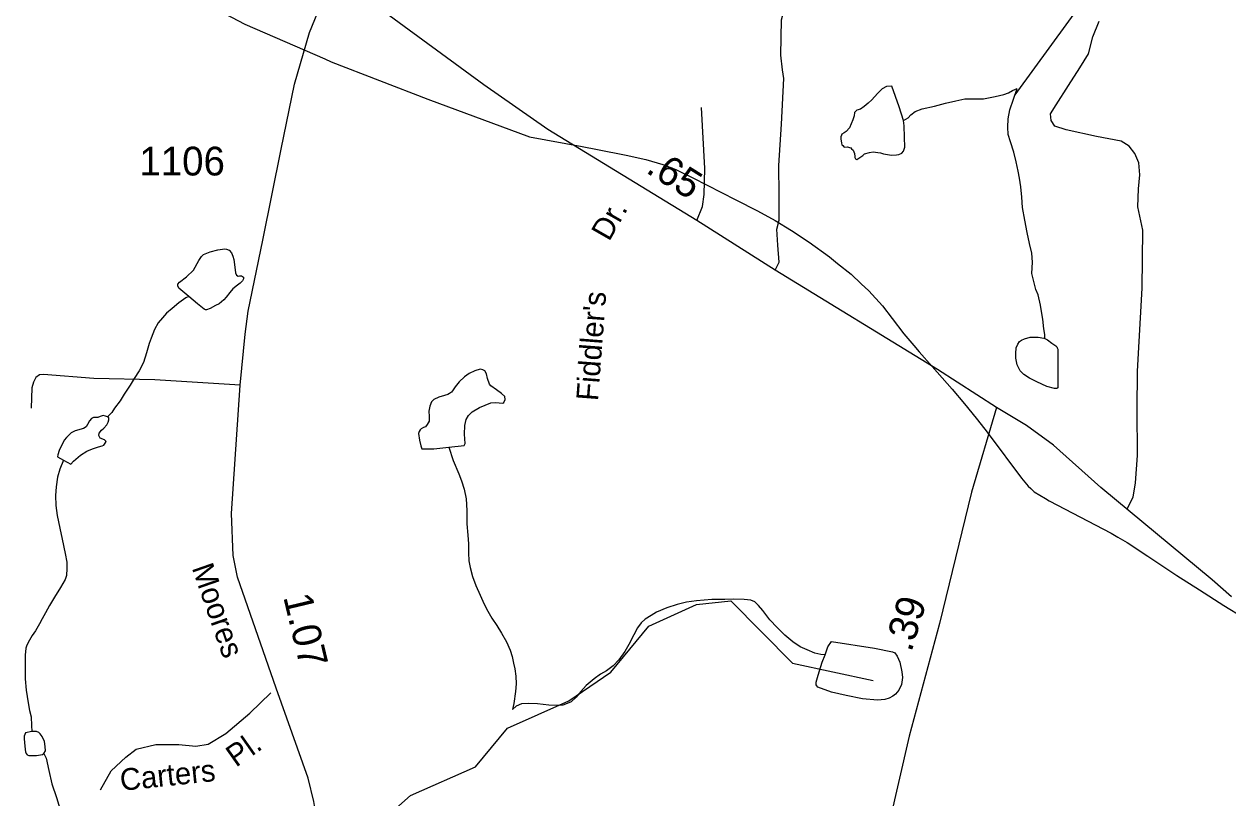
# Model space of a CAD drawing. Extents: x 2126262 to 2293712, y 749403 to 919119.
# Drawn here: x 2171233 to 2176471, y 814779 to 818143 of the extents above; entities that cross this region are included whole.
import ezdxf

# ---------------------------------------------------------------- set-up
doc = ezdxf.new("R2010")
doc.units = 0
for name, color, linetype in [('Exist Hydrographic Creek Single Shore', 7, 'Continuous'), ('Exist Hydrographic Misc Water Feature', 7, 'Continuous'), ('Exist Road Non-System Type 51', 7, 'Continuous'), ('Exist Road Non-System Type 51 Label', 7, 'Continuous'), ('Exist Road Secondary Mileage Hundredths English Label', 7, 'Continuous'), ('Exist Road Secondary Type 51 Attributed', 7, 'Continuous'), ('Exist Road Secondary Type 51 Label', 7, 'Continuous'), ('Exist Road Secondary Type 51 Number Label', 7, 'Continuous')]:
    doc.layers.add(name, color=color, linetype=linetype)

msp = doc.modelspace()

# ---------------------------------------------------------------- linework, layer by layer
at = {"layer": 'Exist Hydrographic Creek Single Shore'}
msp.add_lwpolyline([(2171499.6, 814356), (2171665.7, 814539.5), (2171815.6, 814588.9), (2171948.7, 814582.9), (2172168.9, 814545.8), (2172252.6, 814528.2), (2172286.8, 814534.4), (2172309.5, 814522), (2172367.5, 814522), (2172416.1, 814524.1), (2172430.6, 814507.5), (2172454.4, 814509.6), (2172509.2, 814516.8), (2172656.7, 814561.7), (2172913.6, 814789.3), (2173196.6, 814914.7), (2173336.7, 815082.4), (2173602.6, 815201.6), (2173785.7, 815325.8), (2173950.6, 815525.8), (2174158.7, 815619.9), (2174308.6, 815636.5), (2174576.6, 815365.2), (2174926.6, 815289.1)], dxfattribs=at)
at = {"layer": 'Exist Hydrographic Misc Water Feature'}
for p, q in [((2172541.4, 817992.3), (2172569.5, 817980)), ((2174571.4, 817245.7), (2174648.5, 817195))]:
    msp.add_line(p, q, dxfattribs=at)
for points in [[(2175545.7, 817835.3), (2176000.7, 818462.3), (2176057.7, 818680.9), (2176131.7, 818820.5), (2176239.8, 818906.8), (2176297.6, 818987.6), (2176369.4, 819487.4)], [(2171958.4, 818267.5), (2172193.4, 818143.6), (2172541.4, 817992.3)], [(2171958.4, 818267.5), (2172193.4, 818143.6), (2172541.4, 817992.3)], [(2172569.5, 817980), (2172989.2, 817816.7), (2173431.3, 817653.3), (2173661.4, 817611.7), (2173728.2, 817598.4)], [(2172569.5, 817980), (2172989.2, 817816.7), (2173431.3, 817653.3), (2173661.4, 817611.7), (2173728.2, 817598.4)], [(2175058.8, 817724.4), (2175040.6, 817784.3), (2175008.2, 817874.1), (2174986, 817872), (2174966.1, 817861.8), (2174946, 817841.7), (2174922.2, 817813.6), (2174906.2, 817799.5), (2174888.6, 817785.4), (2174872.6, 817773.3), (2174856.6, 817769.3), (2174850.5, 817763.2), (2174846.6, 817759.2), (2174844.7, 817745.2), (2174838.8, 817727.2), (2174825, 817693.1), (2174809.1, 817677), (2174801.1, 817671), (2174791.4, 817664.9), (2174789.4, 817660.9), (2174787.3, 817652.9), (2174787.3, 817642.9), (2174789.4, 817626.9), (2174791.6, 817618.9), (2174795.5, 817614.9), (2174801.7, 817609), (2174813.6, 817609.1), (2174829.6, 817605.1), (2174833.7, 817601.2), (2174839.6, 817595.2), (2174845.6, 817581.3), (2174847.8, 817567.3), (2174847.8, 817563.3), (2174849.9, 817557.3), (2174855.8, 817555.3), (2174859.9, 817557.3), (2174869.7, 817563.4), (2174881.8, 817571.5), (2174889.6, 817579.5), (2174911.6, 817585.6), (2174927.6, 817587.7), (2174947.7, 817585.8), (2174959.6, 817583.9), (2174971.7, 817579.9), (2175007.5, 817574.1), (2175029.5, 817574.3), (2175039.5, 817576.3), (2175051.6, 817582.4), (2175059.6, 817590.4), (2175065.6, 817608.4), (2175063.3, 817652.5), (2175062.9, 817700.4), (2175058.8, 817724.4)], [(2175058.8, 817724.4), (2175078.9, 817736.5), (2175090.6, 817748.6), (2175110.5, 817762.7), (2175140.6, 817774.8), (2175194.3, 817787.1), (2175242.3, 817799.4), (2175286.4, 817809.6), (2175326.4, 817817.9), (2175364.1, 817818.1), (2175408, 817818.3), (2175458, 817828.6), (2175496, 817836.9), (2175516.1, 817844.9), (2175533.9, 817855), (2175553.8, 817863.2)], [(2175673.8, 816776.1), (2175673.8, 816794.1), (2175669.7, 816818.1), (2175665.6, 816860), (2175659.4, 816894), (2175655.1, 816922), (2175644.8, 816965.9), (2175634.8, 816989.8), (2175626.6, 817023.8), (2175618.4, 817059.7), (2175620, 817107.7), (2175617.8, 817147.7), (2175607.5, 817189.6), (2175597.3, 817237.6), (2175587, 817291.5), (2175576.8, 817345.4), (2175574.5, 817391.4), (2175570.4, 817435.3), (2175564.1, 817473.2), (2175557.9, 817503.3), (2175549.5, 817545.2), (2175539.2, 817587.2), (2175525.1, 817631), (2175515, 817663), (2175512.8, 817695), (2175514.6, 817730.9), (2175522.2, 817771), (2175538, 817817), (2175553.8, 817863.2)], [(2173728.2, 817598.4), (2173853.1, 817573.7), (2173938.4, 817554.4), (2174011.4, 817533.7), (2174069.2, 817511.2), (2174143.2, 817475.2), (2174330.3, 817379.9)], [(2173728.2, 817598.4), (2173853.1, 817573.7), (2173938.4, 817554.4), (2174011.4, 817533.7), (2174069.2, 817511.2), (2174143.2, 817475.2), (2174330.3, 817379.9)], [(2174330.3, 817379.9), (2174423.3, 817331), (2174500.2, 817288.9), (2174571.4, 817245.7)], [(2174330.3, 817379.9), (2174423.3, 817331), (2174500.2, 817288.9), (2174571.4, 817245.7)], [(2171950, 816959.2), (2171905.7, 816995.1), (2171901.8, 817005), (2171901.8, 817012.8), (2171909.6, 817020.9), (2171939.6, 817045.1), (2171969.3, 817073.1), (2171992.9, 817115.4), (2172005.2, 817133.4), (2172013, 817141.6), (2172043.1, 817153.7), (2172075.1, 817161.8), (2172106.7, 817165.9), (2172112.8, 817164.2), (2172124.9, 817160), (2172134.8, 817148.3), (2172140.9, 817134.4), (2172145, 817120.4), (2172147.3, 817110.4), (2172153.2, 817062.4), (2172157.5, 817052.4), (2172163.7, 817048.2), (2172169.6, 817048.5), (2172179.5, 817048.6), (2172183.8, 817046.4), (2172187.7, 817042.5), (2172187.7, 817036.5), (2172183.4, 817026.5), (2172173.7, 817016.6), (2172161.6, 817008.3), (2172141.5, 816992.3), (2172127.8, 816976.1), (2172112.2, 816956.2), (2172102, 816943.9), (2172081.9, 816927.9), (2172066.1, 816919.7), (2172042.5, 816907.5), (2172026.3, 816901.8), (2172022.4, 816901.6), (2172016.2, 816903.7), (2171987.9, 816927.5), (2171950, 816959.2)], [(2174648.5, 817195), (2174737.3, 817131), (2174772.6, 817102.9)], [(2174648.5, 817195), (2174737.3, 817131), (2174772.6, 817102.9)], [(2174772.6, 817102.9), (2174831.4, 817056.1), (2174875.7, 817014.6)], [(2174772.6, 817102.9), (2174831.4, 817056.1), (2174875.7, 817014.6)], [(2174875.7, 817014.6), (2174908.3, 816984.1), (2174968.4, 816918.3), (2175010.2, 816862.8)], [(2174875.7, 817014.6), (2174908.3, 816984.1), (2174968.4, 816918.3), (2175010.2, 816862.8)], [(2171950, 816959.2), (2171936.1, 816953.2), (2171906.1, 816930.9), (2171876.6, 816906.6), (2171852.4, 816886.7), (2171834.6, 816866.7), (2171816.5, 816844.3), (2171800.7, 816816.3), (2171785.1, 816778.4), (2171777.4, 816754.5), (2171765.1, 816714.1), (2171751.7, 816672.3), (2171733.9, 816636.1), (2171711.9, 816602), (2171694.1, 816573.9), (2171668.3, 816534), (2171650.4, 816505.9), (2171626.8, 816473.4), (2171615, 816455.3), (2171607.2, 816447.5), (2171595.1, 816435.5)], [(2175010.2, 816862.8), (2175060.2, 816796.7), (2175104.1, 816745.6)], [(2175010.2, 816862.8), (2175060.2, 816796.7), (2175104.1, 816745.6)], [(2175104.1, 816745.6), (2175127.3, 816718.4), (2175184.7, 816654.1)], [(2175104.1, 816745.6), (2175127.3, 816718.4), (2175184.7, 816654.1)], [(2175673.8, 816776.1), (2175686.1, 816770.2), (2175704.1, 816756.2), (2175722.1, 816744.4), (2175726, 816740.4), (2175728.1, 816736.4), (2175730.1, 816730.4), (2175730.6, 816656.4), (2175731, 816562.5), (2175727.1, 816558.5), (2175717, 816558.5), (2175683, 816568.2), (2175639.1, 816587.9), (2175606.9, 816603.7), (2175582.9, 816619.6), (2175566.7, 816635.6), (2175554.6, 816661.5), (2175548.3, 816691.4), (2175548.3, 816711.4), (2175550.1, 816735.4), (2175556.1, 816751.4), (2175564.1, 816763.5), (2175572.1, 816769.6), (2175586, 816775.6), (2175609.8, 816781.8), (2175645.9, 816781.9), (2175669.9, 816778.1), (2175673.8, 816776.1)], [(2173081.3, 816303.7), (2173147.1, 816312), (2173151.4, 816319.9), (2173149.2, 816360), (2173151, 816398.3), (2173156.5, 816424.2), (2173166.8, 816442.1), (2173182.6, 816458.4), (2173214.6, 816476.3), (2173238.4, 816486.5), (2173264.2, 816496.8), (2173286.1, 816498.7), (2173299.9, 816497), (2173316.3, 816495), (2173319.8, 816498.9), (2173326.1, 816510.9), (2173324.1, 816525), (2173309.9, 816536.9), (2173288, 816552.8), (2173263.8, 816570.7), (2173257.8, 816578.5), (2173249.4, 816602.4), (2173245.5, 816622.5), (2173237.3, 816636.3), (2173229.5, 816640.4), (2173217, 816642.6), (2173193.4, 816636.5), (2173169.9, 816624.2), (2173149.6, 816609.8), (2173126, 816587.9), (2173107.9, 816565.8), (2173096.3, 816549.7), (2173092.4, 816543.8), (2173084.2, 816537.8), (2173076.2, 816533.7), (2173061.8, 816529.4), (2173038, 816521.2), (2173016.3, 816511.1), (2173006.2, 816501.3), (2172998, 816483), (2172994.3, 816461.3), (2172994.8, 816437.3), (2172994.8, 816417.4), (2172986.8, 816403.2), (2172978.8, 816393), (2172971, 816389), (2172960.9, 816383.2), (2172956.8, 816378.9), (2172951.3, 816372.9), (2172949.2, 816363), (2172953.3, 816334.8), (2172959.3, 816309.2), (2172963.2, 816297.2), (2173015.1, 816297.5), (2173081.3, 816303.7)], [(2175184.7, 816654.1), (2175271.2, 816556.9), (2175325.4, 816493)], [(2175184.7, 816654.1), (2175271.2, 816556.9), (2175325.4, 816493)], [(2175325.4, 816493), (2175376.2, 816430.4), (2175413.5, 816381.8)], [(2175325.4, 816493), (2175376.2, 816430.4), (2175413.5, 816381.8)], [(2171595.1, 816435.5), (2171587.1, 816439.2), (2171576.8, 816441.1), (2171563.1, 816437.2), (2171553, 816433), (2171543.2, 816432.9), (2171535, 816432.9), (2171526.8, 816428.8), (2171517.1, 816418.9), (2171509.4, 816403.1), (2171503.4, 816393), (2171491.3, 816384.7), (2171455.2, 816374.7), (2171437.8, 816366.4), (2171425.5, 816354.5), (2171417.5, 816346.4), (2171407.9, 816334.4), (2171385.9, 816290.2), (2171380.2, 816270.1), (2171377.9, 816262.3), (2171404, 816248.2)], [(2171404, 816248.2), (2171436.4, 816230.7), (2171448.2, 816242.7), (2171478, 816268.7), (2171505.7, 816286.8), (2171529.9, 816296.9), (2171555.9, 816305.2), (2171571.9, 816309.2), (2171579.7, 816313.3), (2171585.8, 816321.3), (2171589.7, 816329.3), (2171583.4, 816335.5), (2171563.5, 816343.4), (2171557.3, 816355.2), (2171559.6, 816365), (2171569.2, 816377.4), (2171579.3, 816387.2), (2171593.2, 816401.3), (2171599, 816413.4), (2171601, 816423.3), (2171601.2, 816431.4), (2171595.1, 816435.5)], [(2175413.5, 816381.8), (2175431.4, 816358.4), (2175572.5, 816169.7), (2175601.4, 816135.2), (2175612.7, 816125)], [(2175413.5, 816381.8), (2175431.4, 816358.4), (2175572.5, 816169.7), (2175601.4, 816135.2), (2175612.7, 816125)], [(2173081.3, 816303.7), (2173099.5, 816245.8), (2173123.9, 816188.1), (2173136, 816157.9), (2173148.3, 816122), (2173156.5, 816080.1), (2173159, 816028.2), (2173159.2, 815970.2), (2173163.5, 815922.1), (2173165.8, 815884.5), (2173165.8, 815844.3), (2173168.2, 815810.2), (2173174.4, 815780.5), (2173184.4, 815742.5), (2173198.8, 815702.6), (2173216.8, 815660.5), (2173235.3, 815620.8), (2173251.1, 815590.8), (2173267.5, 815561.1), (2173289.6, 815528.9), (2173309.5, 815495.1), (2173332.1, 815457.2), (2173348.3, 815421.5), (2173356.3, 815393.5), (2173362.6, 815365.4), (2173368.6, 815339.7), (2173373.1, 815307.8), (2173373.3, 815275.7), (2173371, 815241.6), (2173363.6, 815189.6), (2173357.5, 815163.7)], [(2171404, 816248.2), (2171388.6, 816208.3), (2171378.5, 816174.1), (2171372.8, 816132), (2171369.1, 816094), (2171371.6, 816050.2), (2171377.3, 816006.4), (2171388, 815952.4), (2171397.8, 815904.3), (2171412.2, 815842.5), (2171418.5, 815804.6), (2171418.5, 815776.6), (2171417.1, 815746.4), (2171411.1, 815728.6), (2171391.2, 815694.3), (2171365.6, 815652.3), (2171343.9, 815616.2), (2171325.8, 815584.1), (2171312.1, 815558.2), (2171300, 815536.1), (2171282.2, 815505.9), (2171268.6, 815485.6), (2171256.3, 815465.6), (2171244.6, 815443.8), (2171240.5, 815429.9), (2171236.8, 815399.6), (2171237.3, 815353.7), (2171237.7, 815297.6), (2171241.8, 815247.9), (2171250, 815191.9), (2171256.3, 815159.7), (2171264.1, 815131.8), (2171264.5, 815093.9), (2171266.6, 815068)], [(2175612.7, 816125), (2175628, 816110.6), (2175676.6, 816080.6)], [(2175612.7, 816125), (2175628, 816110.6), (2175676.6, 816080.6)], [(2175676.6, 816080.6), (2175692.4, 816070.8), (2175962.3, 815930.6), (2175992, 815913)], [(2175676.6, 816080.6), (2175692.4, 816070.8), (2175962.3, 815930.6), (2175992, 815913)], [(2175992, 815913), (2176032.2, 815889.2), (2176122, 815829.9)], [(2175992, 815913), (2176032.2, 815889.2), (2176122, 815829.9)], [(2176122, 815829.9), (2176248.3, 815746.4), (2176346.9, 815683.3)], [(2176122, 815829.9), (2176248.3, 815746.4), (2176346.9, 815683.3)], [(2174717.8, 815401), (2174700, 815402.9), (2174673.7, 815408.9), (2174639.9, 815422.6), (2174609.7, 815436.5), (2174577.3, 815458.4), (2174543.3, 815486.2), (2174509.5, 815519.8), (2174477.3, 815553.9), (2174446.9, 815593.7), (2174428.9, 815615.5), (2174412.9, 815631.4), (2174394.6, 815639.4), (2174366.3, 815641.2), (2174320.8, 815642.8), (2174282.5, 815642.5), (2174224.7, 815642.3), (2174159, 815636), (2174114.7, 815629.8), (2174074.8, 815619.6), (2174029, 815605.4), (2173985.2, 815586.9), (2173961.2, 815572.7), (2173935.5, 815556.7), (2173917.1, 815540.8), (2173901.5, 815518.4), (2173885.5, 815488.3), (2173863.6, 815446.3), (2173846.3, 815416.4), (2173820.3, 815380.2), (2173796.3, 815354.1), (2173766.8, 815331.8), (2173740.5, 815317.5), (2173713, 815297.4), (2173679, 815267.2), (2173655.2, 815241.2), (2173635.5, 815217), (2173613.4, 815196.8), (2173595.6, 815189), (2173577.5, 815182.8), (2173551.7, 815180.6), (2173515.4, 815182.4), (2173467.4, 815188), (2173427.8, 815190), (2173397.3, 815187.7), (2173373.5, 815177.5), (2173357.5, 815163.7)], [(2176346.9, 815683.3), (2176453.4, 815615.4), (2176538.3, 815562.9), (2176690.4, 815474.6), (2176783.7, 815422.3)], [(2176346.9, 815683.3), (2176453.4, 815615.4), (2176538.3, 815562.9), (2176690.4, 815474.6), (2176783.7, 815422.3)], [(2174717.8, 815401), (2174729.9, 815435.3), (2174745.3, 815459.4), (2174933.5, 815430.5), (2175012.1, 815414.6), (2175021.9, 815410.6), (2175031.7, 815395), (2175043.8, 815368.8), (2175052.2, 815327), (2175054.3, 815303.1), (2175050.4, 815272.9), (2175038.5, 815247.1), (2175024.8, 815230.9), (2175012.9, 815220.9), (2174996.7, 815212.8), (2174978.6, 815206.7), (2174946.8, 815204.5), (2174880.6, 815210.1), (2174809.1, 815223.8), (2174746.5, 815239.3), (2174686.4, 815260.9), (2174682.3, 815266.8), (2174678.8, 815271), (2174678.6, 815282.8), (2174688.3, 815313), (2174706.1, 815369.2), (2174717.8, 815401)], [(2171266.6, 815068), (2171238.9, 815061.7), (2171232.7, 815047.6), (2171233.1, 815035.8), (2171234.8, 815019.7), (2171237, 814989.8), (2171239.3, 814979.7), (2171241.4, 814971.7), (2171245.5, 814965.8), (2171253, 814963.8), (2171287.1, 814963.9), (2171313.3, 814968.1), (2171319.1, 814972.1)], [(2171319.1, 814972.1), (2171325.4, 814984.1), (2171325, 815002.4), (2171320.9, 815024.2), (2171311.1, 815046.4), (2171302.9, 815058.1), (2171296.5, 815063.9), (2171287.1, 815067.8), (2171266.6, 815068)], [(2171319.1, 814972.1), (2171329.3, 814952.3), (2171340, 814898.4), (2171354.1, 814840.6), (2171374.4, 814780.8), (2171388.4, 814732.8), (2171402.5, 814684.8), (2171410.9, 814632.8), (2171419.3, 814598.7), (2171427.5, 814567), (2171438, 814537.1), (2171451.5, 814509), (2171462, 814487.2), (2171474.1, 814461.4), (2171476.3, 814439.1), (2171478.4, 814417.4)]]:
    msp.add_lwpolyline(points, dxfattribs=at)
at = {"layer": 'Exist Road Non-System Type 51'}
for points in [[(2174501.1, 817073.8), (2174518.4, 817108.1), (2174512.8, 817182.1), (2174508.6, 817251.9), (2174518.4, 817291), (2174518.4, 817401.3), (2174516.3, 817529), (2174528.8, 817707.7), (2174539.3, 817906.7), (2174532.3, 817944.4), (2174525.3, 818008.7), (2174528.1, 818162.3), (2174541.4, 818210.4), (2174549.7, 818362.7), (2174556.7, 818440.9)], [(2176032.4, 816035.6), (2176059.3, 816087.2), (2176069, 816148.7), (2176077.4, 816267.4), (2176075.3, 816467.8), (2176078.1, 816634), (2176097.6, 816995.6), (2176100.4, 817247), (2176079.5, 817348.9), (2176082.3, 817427.1), (2176087.9, 817488.6), (2176083, 817539.6), (2176066.3, 817581.5), (2176041.1, 817612.2), (2176006.3, 817634.5), (2175898.8, 817654.1), (2175767.7, 817683.4), (2175717.4, 817700.1), (2175702.1, 817723.9), (2175699.3, 817753.2), (2175723, 817792.3), (2175776.7, 817876.8), (2175827, 817953.6), (2175864.6, 818013.7), (2175882.8, 818087.7), (2175910.7, 818156.1)], [(2174159.9, 817289.6), (2174184.3, 817351), (2174191.3, 817402.7), (2174195.5, 817515.8), (2174180, 817780.5)], [(2172173, 816573.3), (2171801.6, 816596.1), (2171536.8, 816603.3), (2171317, 816619.8), (2171299.4, 816618.8), (2171283.9, 816607.4), (2171273.5, 816586.7), (2171266.3, 816561.9), (2171263.2, 816474)], [(2171565, 814815), (2171611.1, 814896.3), (2171674.9, 814955.7), (2171721, 814990.9), (2171806.7, 815010.7), (2171905.6, 815010.7), (2171980.4, 815004.1), (2172033.1, 815012.9), (2172110, 815059.1), (2172215.5, 815147), (2172306.9, 815236.2)]]:
    msp.add_lwpolyline(points, dxfattribs=at)
at = {"layer": 'Exist Road Secondary Type 51 Attributed'}
for points in [[(2171783.8, 812953.2), (2171840.9, 813103.7), (2171970.5, 813314.3), (2172150.7, 813719.6), (2172293, 813979.3), (2172416.5, 814238.4), (2172497.3, 814434.1), (2172509.2, 814516.8), (2172506.3, 814685.9), (2172493.2, 814763), (2172469.4, 814864.4), (2172329.7, 815256.4), (2172162.1, 815739.5), (2172142, 815832.6), (2172135.2, 816015.7), (2172173, 816573.3), (2172194.2, 816795.7), (2172208.2, 816896), (2172271.3, 817203.3), (2172352, 817599.5), (2172408.9, 817882.9), (2172474.5, 818106.3), (2172537.6, 818260.5), (2172583.2, 818338.1)], [(2175464.5, 816476.8), (2175207.1, 816642.3), (2174501.1, 817073.8), (2174159.9, 817289.6), (2173511.1, 817684.8), (2173233.4, 817878.9), (2172783.8, 818207.7), (2172583.2, 818338.1)], [(2175464.5, 816476.8), (2175355.4, 816108.8), (2175215.9, 815537.8), (2175084.1, 815048.3), (2174995.5, 814663.6), (2174943.1, 814472.3)], [(2176486.5, 815653.6), (2176402.8, 815727.6), (2175917.3, 816128.4), (2175711.5, 816312.1), (2175594.3, 816398.6), (2175464.5, 816476.8)]]:
    msp.add_lwpolyline(points, dxfattribs=at)

# ---------------------------------------------------------------- texts
at = {"layer": 'Exist Road Non-System Type 51 Label'}
for s, rotation, p in [('Dr.', 60.2739, (2173778.3, 817195.2)), ("Fiddler's", 85.6285, (2173729.7, 816502.9)), ('Pl.', 35.1867, (2172154.6, 814910.1)), ('Carters', 6.0363, (2171654.9, 814809.5))]:
    msp.add_text(s, height=95, rotation=rotation, dxfattribs=at).set_placement(p)
at = {"layer": 'Exist Road Secondary Mileage Hundredths English Label'}
for s, rotation, p in [('.65', 327.7814, (2173933.6, 817500.6)), ('1.07', 283.4216, (2172360, 815652.9)), ('.39', 73.1748, (2175093.5, 815409.7))]:
    msp.add_text(s, height=125, rotation=rotation, dxfattribs=at).set_placement(p)
at = {"layer": 'Exist Road Secondary Type 51 Label'}
msp.add_text('Moores', height=95, rotation=289.2165, dxfattribs=at).set_placement((2171961.6, 815779.5))
at = {"layer": 'Exist Road Secondary Type 51 Number Label'}
msp.add_text('1106', height=125, dxfattribs=at).set_placement((2171734.7, 817485.3))

doc.saveas('drawing.dxf')
